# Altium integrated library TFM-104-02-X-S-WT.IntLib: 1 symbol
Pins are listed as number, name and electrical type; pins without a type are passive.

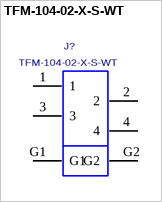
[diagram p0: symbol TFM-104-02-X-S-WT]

## TFM-104-02-X-S-WT
designator J?
.050 C.L. SINGLE ROW SHROUDED TERMINAL STRIP, SURFACE MOUNT.; MANUFACTURER: SAMTEC
footprint TFM-104-02-X-S-WT
pins: 1, 2, 3, 4, G1, G2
